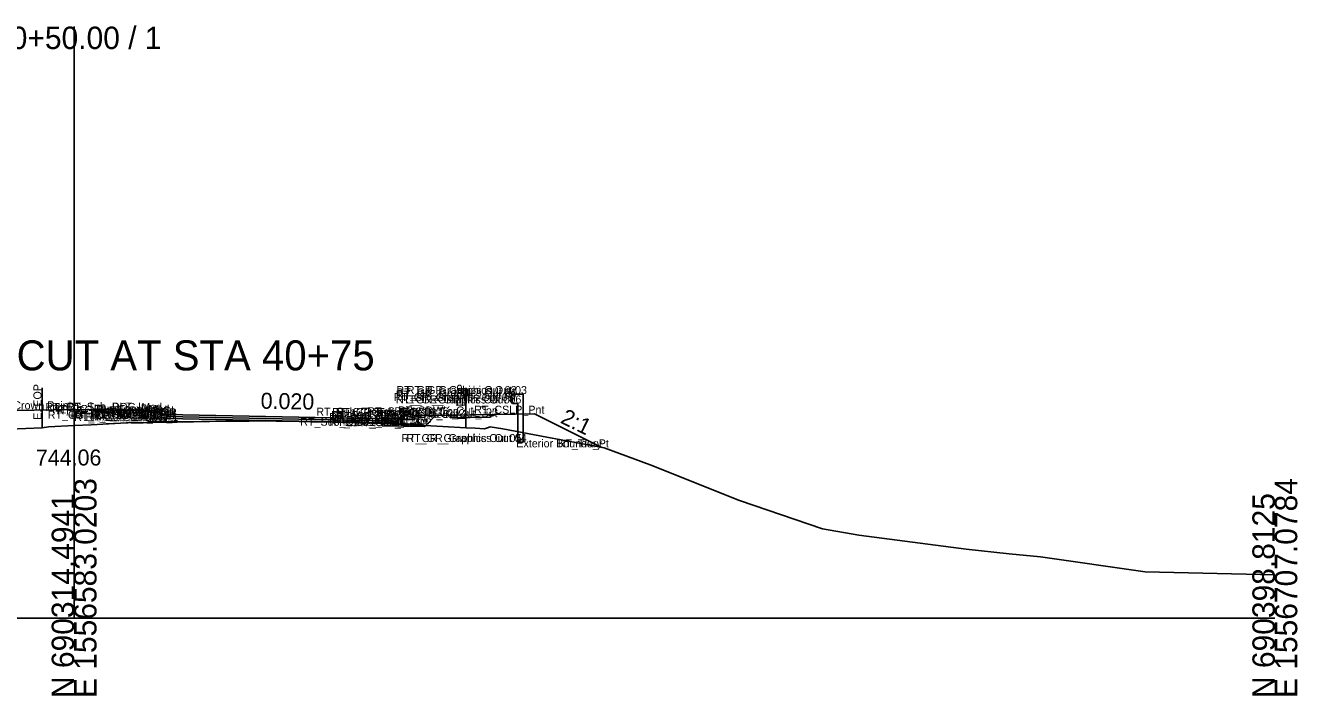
# Model space of a CAD drawing. Extents: x -26 to 6300, y -10 to 9577.
# Drawn here: x 143.9 to 302.8, y 6990.3 to 7074.1 of the extents above; entities that cross this region are included whole.
import ezdxf

# ---------------------------------------------------------------- set-up
doc = ezdxf.new("R2010")
doc.units = 0
for name, color, linetype in [('Default', 7, 'Continuous'), ('Exist CMT Pavement', 7, 'Continuous'), ('Exist Cross Section Cell', 7, 'Continuous'), ('Exist XS Center Line Elevation Label', 7, 'Continuous'), ('Exist XS Ground Line', 7, 'Continuous'), ('Prop CMT Conc Surface', 7, 'Continuous'), ('Prop CMT Concrete Structures', 7, 'Continuous'), ('Prop CMT Guardrail Graphics', 7, 'Continuous'), ('Prop CMT Pvmt Course 1', 7, 'Continuous'), ('Prop CMT Pvmt Course 1 CG', 7, 'Continuous'), ('Prop CMT Pvmt Course 2', 7, 'Continuous'), ('Prop CMT Pvmt Course 3', 7, 'Continuous'), ('Prop CMT Pvmt Surface', 7, 'Continuous'), ('Prop CMT Slope Grass', 7, 'Continuous'), ('Prop CMT Subgrade Earthwork', 7, 'Continuous'), ('Prop XS Label Text', 7, 'Continuous'), ('Prop XS SE Text', 7, 'Continuous'), ('Prop XS Side Slope Text', 7, 'Continuous'), ('Prop XSC Text', 7, 'Continuous')]:
    doc.layers.add(name, color=color, linetype=linetype)

msp = doc.modelspace()

# ---------------------------------------------------------------- linework, layer by layer
at = {"layer": 'Exist CMT Pavement'}
msp.add_lwpolyline([(164.25, 7024.52), (165.92, 7024.56), (168.97, 7024.62), (170.42, 7024.62), (171.88, 7024.62), (173.08, 7024.63), (174.77, 7024.63), (175.24, 7024.61), (176.57, 7024.59), (179.62, 7024.53), (182.67, 7024.46), (185.71, 7024.38), (188.5, 7024.31)], dxfattribs=at)
at = {"layer": 'Exist Cross Section Cell'}
for p, q in [((150, 7000), (150, 7073.91)), ((0, 7000), (150, 7000)), ((150, 7000), (300, 7000))]:
    msp.add_line(p, q, dxfattribs=at)
at = {"layer": 'Exist XS Ground Line'}
msp.add_lwpolyline([(141.93, 7023.62), (146.02, 7023.77), (146.81, 7023.9), (150, 7024.05), (152.13, 7024.15), (156.55, 7024.39), (162.86, 7024.49), (168.97, 7024.62), (171.88, 7024.62), (174.29, 7024.64), (175.24, 7024.61), (176.57, 7024.59), (182.67, 7024.46), (188.74, 7024.31), (190.87, 7024.2), (193.07, 7024.09), (196.06, 7023.92), (198.94, 7023.76), (200.1, 7023.71), (201.26, 7023.64), (201.63, 7023.76), (201.97, 7023.9), (203.55, 7023.63), (209.07, 7022.59), (216.21, 7021.28), (221.98, 7019.16), (233.14, 7014.67), (243.5, 7011.13), (248.02, 7010.37), (261.44, 7008.6), (266.81, 7008.01), (270.71, 7007.64), (283.8, 7005.79), (300, 7005.4)], dxfattribs=at)
at = {"layer": 'Prop CMT Conc Surface'}
for points in [[(161.5, 7025.45), (160.75, 7025.47), (160.75, 7025.63), (159.99, 7025.88)], [(190.5, 7024.87), (192.5, 7024.75)], [(192.5, 7024.75), (192.5, 7025.25), (193, 7025.25)], [(197, 7025.34), (202, 7025.44)]]:
    msp.add_lwpolyline(points, dxfattribs=at)
at = {"layer": 'Prop CMT Concrete Structures'}
for points in [[(161.5, 7025.45), (160.75, 7025.47), (160.75, 7025.63), (159.99, 7025.88)], [(159.99, 7025.88), (159.99, 7024.9)], [(159.99, 7024.9), (161.5, 7024.87)], [(161.5, 7024.87), (161.5, 7025.45)], [(190.5, 7024.87), (192.5, 7024.75), (192.5, 7025.25), (193, 7025.25)], [(193, 7025.25), (193, 7024.24), (190.5, 7024.29)], [(190.5, 7024.29), (190.5, 7024.87)], [(202, 7025.44), (197, 7025.34)], [(197, 7025.34), (197, 7025.01)], [(197, 7025.01), (202, 7025.11)], [(202, 7025.11), (202, 7025.44)]]:
    msp.add_lwpolyline(points, dxfattribs=at)
at = {"layer": 'Prop CMT Guardrail Graphics'}
for points in [[(206.1, 7027.99), (204.77, 7027.99), (204.5, 7027.69)], [(204.5, 7027.69), (204.77, 7027.4)], [(204.77, 7027.4), (204.5, 7027.11)], [(206.1, 7021.99), (206.1, 7027.99)], [(204.5, 7027.11), (204.77, 7026.82), (205.44, 7026.82)], [(205.44, 7026.82), (205.44, 7021.99)], [(205.44, 7021.99), (206.1, 7021.99)]]:
    msp.add_lwpolyline(points, dxfattribs=at)
at = {"layer": 'Prop CMT Pvmt Course 1'}
for points in [[(161.5, 7025.45), (190.5, 7024.87)], [(161.5, 7025.2), (161.5, 7025.45)], [(190.5, 7024.62), (161.5, 7025.2)], [(161.5, 7025.2), (161.5, 7025.2), (161.5, 7025.2)], [(188.5, 7024.91), (188.5, 7024.66)], [(190.5, 7024.87), (190.5, 7024.62)]]:
    msp.add_lwpolyline(points, dxfattribs=at)
at = {"layer": 'Prop CMT Pvmt Course 1 CG'}
for points in [[(161.5, 7024.87), (159.49, 7024.91), (159.2, 7024.62)], [(159.24, 7024.62), (161.5, 7024.58)], [(161.5, 7024.62), (161.5, 7024.87)], [(190.5, 7024.29), (193.5, 7024.23), (193.8, 7023.93)], [(190.5, 7024.04), (190.5, 7024.29)], [(193.8, 7023.93), (188.5, 7024.04)]]:
    msp.add_lwpolyline(points, dxfattribs=at)
at = {"layer": 'Prop CMT Pvmt Course 2'}
for points in [[(161.5, 7024.95), (161.5, 7025.2)], [(161.5, 7025.2), (190.5, 7024.62)], [(190.5, 7024.37), (161.5, 7024.95)], [(188.5, 7024.66), (188.5, 7024.41)], [(190.5, 7024.62), (190.5, 7024.37)]]:
    msp.add_lwpolyline(points, dxfattribs=at)
at = {"layer": 'Prop CMT Pvmt Course 3'}
for points in [[(161.5, 7024.95), (190.5, 7024.37)], [(161.5, 7024.58), (161.5, 7024.95)], [(164.25, 7024.52), (161.5, 7024.58)], [(188.5, 7024.41), (188.5, 7024.04)], [(190.5, 7024.37), (190.5, 7024)]]:
    msp.add_lwpolyline(points, dxfattribs=at)
at = {"layer": 'Prop CMT Pvmt Surface'}
msp.add_lwpolyline([(161.5, 7025.45), (190.5, 7024.87)], dxfattribs=at)
at = {"layer": 'Prop CMT Slope Grass'}
for points in [[(140.01, 7025.88), (150, 7026.08)], [(159.99, 7025.88), (150, 7026.08)], [(193, 7025.25), (207.5, 7025.54)], [(207.5, 7025.54), (215.92, 7021.33)]]:
    msp.add_lwpolyline(points, dxfattribs=at)
at = {"layer": 'Prop CMT Subgrade Earthwork'}
for p, q in [((188.5, 7024.04), (188.5, 7024.31)), ((193.8, 7023.93), (195.16, 7025.3))]:
    msp.add_line(p, q, dxfattribs=at)
for points in [[(157.9, 7025.93), (159.2, 7024.62)], [(159.2, 7024.62), (161.5, 7024.58)], [(161.5, 7024.58), (161.5, 7024.58)], [(161.5, 7024.58), (164.25, 7024.52)], [(188.5, 7024.04), (193.8, 7023.93)]]:
    msp.add_lwpolyline(points, dxfattribs=at)
at = {"layer": 'Prop XS Label Text'}
for p, q in [((146.02, 7028.77), (146.02, 7023.77)), ((198.94, 7028.76), (198.94, 7023.76))]:
    msp.add_line(p, q, dxfattribs=at)

# ---------------------------------------------------------------- texts
at = {"layer": 'Default'}
for s, p in [('RT_GR_Graphics Out 02', (190.26, 7027.99)), ('RT_GR_Graphics Out 03', (191.56, 7027.99)), ('RT_GR_Graphics Out 08', (189.92, 7027.11)), ('RT_GR_Graphics Out 07', (190.17, 7026.82)), ('RT_GR_Graphics Out 09', (190.2, 7027.4)), ('RT_GR_Graphics Out 01', (190.28, 7027.69)), ('RT_GR_Graphics Out 06', (190.86, 7026.82)), ('MD_Crown Point', (139.58, 7026.08)), ('RT_CG_Top_BOC_Med', (146.43, 7025.88)), ('RT_CG_Bot_BOC_Med', (146.71, 7024.9)), ('RT_CG_Top_Face_Med', (147.25, 7025.63)), ('RT_CG_Top_Gut_Med', (147.8, 7025.47)), ('RT_Sub_DLT_In', (149.07, 7025.93)), ('RT_CG1_Shelf_In', (149.57, 7024.91)), ('RT_CG_Bot_IE_Med', (149.98, 7024.87)), ('RT_PV2_OEEOP', (152.17, 7025.2)), ('RT_PV3_OEEOP', (152.17, 7024.95)), ('RT_PV2_IEEOP', (152.93, 7025.2)), ('RT_PV2_PGL', (154.15, 7025.2)), ('RT_PV1_PGL', (154.38, 7025.45)), ('RT_Sub_Trench_Out_DLT', (180.26, 7025.29)), ('RT_PV1_OEOT', (182.11, 7024.87)), ('RT_CG_Top_Face', (182.22, 7025.25)), ('RT_CG_Top_BOC', (182.69, 7025.25)), ('RT_CG_Top_Gut', (182.75, 7024.75)), ('RT_SDWK_In_Top', (186.62, 7025.34)), ('RT_SDWK_In_Bot', (186.87, 7025.01)), ('RT_SDWK_Out_Top', (190.46, 7025.44)), ('RT_SDWK_Out_Bot', (190.71, 7025.11)), ('RT_CSLP_Pnt', (199.98, 7025.54)), ('RT_Sub_IEOT_CG_1', (150.01, 7024.62)), ('RT_Sub_IEOP', (151.42, 7024.67)), ('RT_Sub_OEEOP', (152.21, 7024.58)), ('RT_Sub_IEEOP', (152.97, 7024.58)), ('RT_Sub_PGL', (154.19, 7024.58)), ('RT_Sub_OEOT_CG_1', (178.25, 7024.04)), ('RT_PV2_OEOT', (181.87, 7024.62)), ('RT_PV3_OEOT', (181.87, 7024.37)), ('RT_Sub_OEOT', (181.92, 7024)), ('RT_CG_Bot_IE', (182.22, 7024.29)), ('RT_CG1_Shelf_Out', (182.36, 7024.23)), ('RT_CG_Bot_BOC', (182.97, 7024.24)), ('RT_Sub_OEOP', (185.17, 7023.97)), ('RT_GR_Graphics Out 05', (190.88, 7021.99)), ('RT_GR_Graphics Out 04', (191.52, 7021.99)), ('Exterior Boundary', (205.24, 7021.33)), ('RT_Tie_Pt', (210.41, 7021.33))]:
    msp.add_text(s, height=1, dxfattribs=at).set_placement(p)
at = {"layer": 'Exist Cross Section Cell'}
msp.add_text('40+50.00 / 1', height=2.8, dxfattribs=at).set_placement((140, 7071.11))
for s, p in [('E 1556583.0203', (152.8, 6990)), ('E 1556707.0784', (302.8, 6990)), ('N 690314.4941', (150, 6990)), ('N 690398.8125', (300, 6990))]:
    msp.add_text(s, height=2.8, rotation=90, dxfattribs=at).set_placement(p)
at = {"layer": 'Exist XS Center Line Elevation Label'}
msp.add_text('744.06', height=2, dxfattribs=at).set_placement((145.23, 7019.06))
at = {"layer": 'Prop XS Label Text'}
for p in [(145.92, 7024.78), (198.84, 7024.78)]:
    msp.add_text('E. EOP', height=1, rotation=90, dxfattribs=at).set_placement(p)
at = {"layer": 'Prop XS SE Text'}
msp.add_text('0.020', height=2, rotation=358.8542, dxfattribs=at).set_placement((173.29, 7026.17))
at = {"layer": 'Prop XS Side Slope Text'}
msp.add_text('2:1', height=2, rotation=333.9281, dxfattribs=at).set_placement((210.63, 7024.44))
at = {"layer": 'Prop XSC Text'}
msp.add_text('END UNDERCUT AT STA 40+75', height=3.75, dxfattribs=at).set_placement((113.01, 7030.95))

doc.saveas('drawing.dxf')
